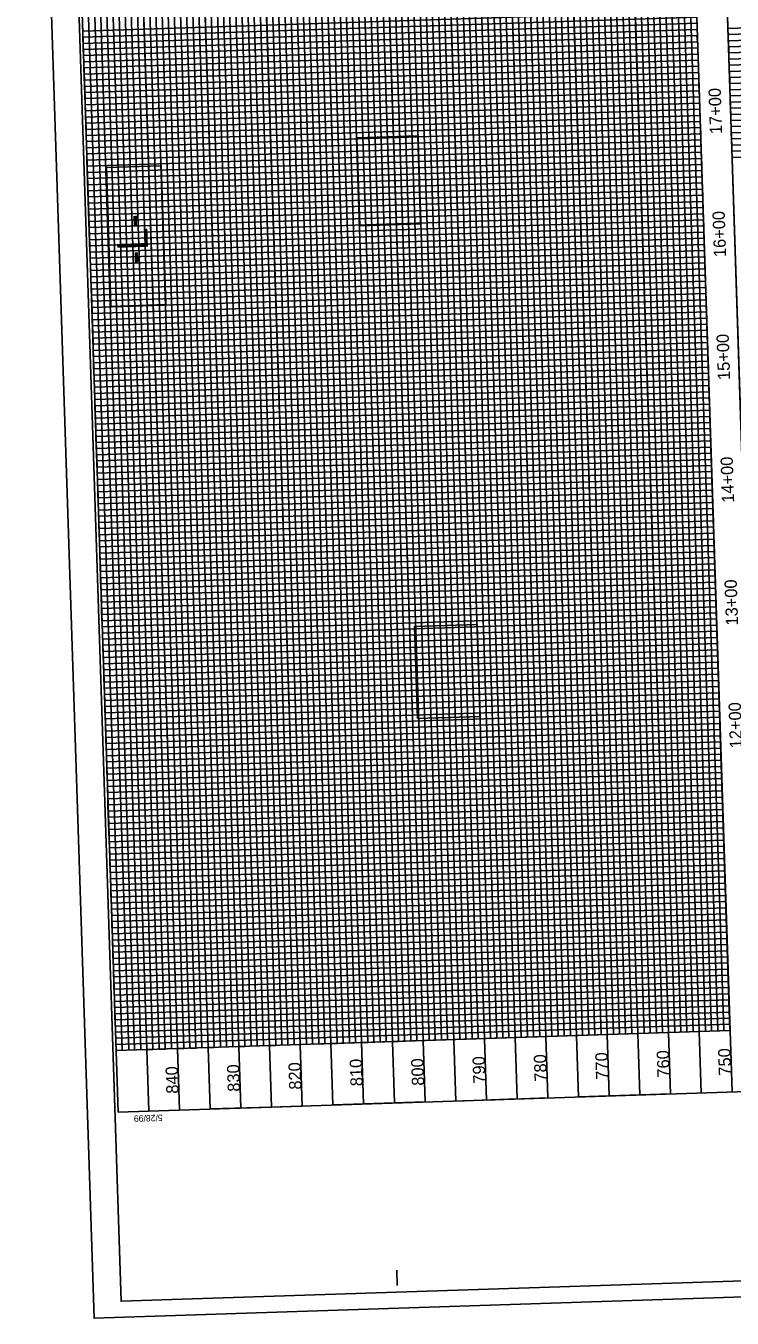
# Model space of a CAD drawing. Extents: x 1627314 to 1628469, y 762309 to 764212.
# Drawn here: x 1627314 to 1627889, y 762309 to 763361 of the extents above; entities that cross this region are included whole.
import ezdxf

# ---------------------------------------------------------------- set-up
doc = ezdxf.new("R2010")
doc.units = 0
for name, color, linetype in [('Exist Vertical Profile Horizontal Axis Label Major', 7, 'Continuous'), ('Exist Vertical Profile Vertical Axis Label', 7, 'Continuous'), ('Prop DSN Text', 7, 'Continuous'), ('Prop Grid Mask', 7, 'Continuous'), ('Sheet DOT Grid CELL', 7, 'Continuous'), ('Sheet Layout Profile Border Port 1', 7, 'Continuous'), ('Sheet Layout Profile Border Port 2', 7, 'Continuous'), ('Sheet Plot Border Inside CELL', 7, 'Continuous'), ('Sheet Plot Border Outside CELL', 7, 'Continuous'), ('Sheet Profile CELL', 7, 'Continuous'), ('Sheet Profile Grid Major CELL', 7, 'Continuous'), ('Sheet Profile Grid Middle CELL', 7, 'Continuous'), ('Sheet Profile Grid Minor CELL', 7, 'Continuous')]:
    doc.layers.add(name, color=color, linetype=linetype)

msp = doc.modelspace()

# ---------------------------------------------------------------- linework, layer by layer
at = {"layer": 'Prop Grid Mask'}
for points in [[(1627586, 763198), (1627583.6, 763269.6), (1627633.2, 763271.3), (1627635.6, 763199.6)], [(1627428.2, 763134), (1627424.5, 763247), (1627379.8, 763245.6), (1627383.5, 763132.5)], [(1627633.1, 762797.2), (1627630.7, 762872), (1627681.6, 762873.7), (1627684.1, 762798.8)]]:
    msp.add_lwpolyline(points, close=True, dxfattribs=at)
at = {"layer": 'Sheet DOT Grid CELL'}
for p, q in [((1627914, 762494.2), (1627865, 763993.3)), ((1627590.1, 763984.4), (1627639.2, 762485.2)), ((1627640.1, 763986), (1627689.2, 762486.8)), ((1627690.1, 763987.7), (1627739.1, 762488.5)), ((1627740.1, 763989.3), (1627789.1, 762490.1)), ((1627790, 763991), (1627839.1, 762491.8)), ((1627546.7, 763782.8), (1627589.2, 762483.6)), ((1627396.8, 763777.9), (1627439.3, 762478.7)), ((1627446.8, 763779.6), (1627489.3, 762480.3)), ((1627496.7, 763781.3), (1627539.2, 762481.9)), ((1627886.3, 763343.8), (1628386, 763360.1)), ((1627861.3, 763342.9), (1627361.5, 763326.6)), ((1627887.9, 763293.8), (1628387.6, 763310.1)), ((1627862.9, 763293), (1627363.2, 763276.6)), ((1627864.5, 763243), (1627364.8, 763226.6)), ((1627866.2, 763193), (1627366.4, 763176.7)), ((1627867.8, 763143), (1627368.1, 763126.7)), ((1627869.4, 763093.1), (1627369.7, 763076.7)), ((1627871.1, 763043.1), (1627371.3, 763026.7)), ((1627872.7, 762993.1), (1627373, 762976.8)), ((1627874.3, 762943.1), (1627374.6, 762926.8)), ((1627876, 762893.2), (1627376.2, 762876.8)), ((1627877.6, 762843.2), (1627377.9, 762826.9)), ((1627879.2, 762793.2), (1627379.5, 762776.9)), ((1627880.9, 762743.3), (1627381.1, 762726.9)), ((1627882.5, 762693.3), (1627382.8, 762676.9)), ((1627884.2, 762643.3), (1627384.4, 762627)), ((1627885.8, 762593.3), (1627386.1, 762577)), ((1627887.4, 762543.4), (1627387.7, 762527))]:
    msp.add_line(p, q, dxfattribs=at)
at = {"layer": 'Sheet Layout Profile Border Port 1'}
msp.add_lwpolyline([(1627386.1, 762577), (1627885.8, 762593.3), (1627841.7, 763942.6), (1627566.8, 763933.6), (1627570.1, 763833.6), (1627345.2, 763826.3)], close=True, dxfattribs=at)
msp.add_lwpolyline([(1627548.7, 762532.3), (1627887.4, 762543.4), (1627841.7, 763942.6), (1627566.8, 763933.6)], dxfattribs=at)
at = {"layer": 'Sheet Layout Profile Border Port 2'}
for points in [[(1627912.4, 762544.2), (1627866.6, 763943.4), (1628366.4, 763959.8), (1628412.1, 762560.5)], [(1627912.4, 762544.2), (1628412.1, 762560.5), (1628366.4, 763959.8), (1627866.6, 763943.4)]]:
    msp.add_lwpolyline(points, close=True, dxfattribs=at)
at = {"layer": 'Sheet Plot Border Inside CELL'}
msp.add_lwpolyline([(1628446.3, 762357.5), (1628391.9, 764023.1), (1627337.3, 763988.6), (1627391.8, 762323)], close=True, dxfattribs=at)
at = {"layer": 'Sheet Plot Border Outside CELL'}
msp.add_lwpolyline([(1628469.2, 762345.3), (1628413.6, 764044.4), (1627314.2, 764008.4), (1627369.8, 762309.3)], close=True, dxfattribs=at)
at = {"layer": 'Sheet Profile CELL'}
for p, q in [((1627889.1, 762493.4), (1627840, 763992.6)), ((1627914, 762494.2), (1627865, 763993.4)), ((1627616.6, 762335.9), (1627616.1, 762348.4))]:
    msp.add_line(p, q, dxfattribs=at)
msp.add_lwpolyline([(1627340.3, 763976.2), (1627389.3, 762477), (1628438.8, 762511.4), (1628389.7, 764010.6)], close=True, dxfattribs=at)
at = {"layer": 'Sheet Profile Grid Major CELL'}
msp.add_line((1627887.9, 763293.8), (1627886.3, 763343.8), dxfattribs=at)
for points in [[(1627546.7, 763782.9), (1627589.2, 762483.6), (1627639.2, 762485.2), (1627590.1, 763984.4)], [(1627640.1, 763986), (1627689.2, 762486.8), (1627739.1, 762488.5), (1627690.1, 763987.7)], [(1627740.1, 763989.3), (1627789.1, 762490.1), (1627789.1, 762490.1), (1627839.1, 762491.8), (1627790, 763991)], [(1627439.3, 762478.7), (1627396.8, 763778)], [(1627446.8, 763779.6), (1627489.3, 762480.3), (1627539.2, 762481.9), (1627496.7, 763781.3)], [(1627387.7, 762527), (1627887.4, 762543.4), (1627885.8, 762593.3), (1627386.1, 762577), (1627384.4, 762627), (1627884.2, 762643.3), (1627882.5, 762693.3), (1627382.8, 762676.9), (1627381.1, 762726.9), (1627880.9, 762743.3), (1627879.2, 762793.2), (1627379.5, 762776.9), (1627377.9, 762826.9), (1627877.6, 762843.2), (1627876, 762893.2), (1627376.2, 762876.8), (1627374.6, 762926.8), (1627874.3, 762943.1), (1627872.7, 762993.1), (1627373, 762976.8), (1627371.3, 763026.7), (1627871.1, 763043.1), (1627869.4, 763093.1), (1627369.7, 763076.7), (1627368.1, 763126.7), (1627867.8, 763143), (1627866.2, 763193), (1627366.4, 763176.7), (1627364.8, 763226.6), (1627864.5, 763243), (1627862.9, 763293), (1627363.2, 763276.6), (1627361.5, 763326.6), (1627861.3, 763342.9), (1627859.6, 763392.9)], [(1628387.6, 763310.1), (1627887.9, 763293.8), (1627886.3, 763343.8), (1628386, 763360.1)]]:
    msp.add_lwpolyline(points, dxfattribs=at)
at = {"layer": 'Sheet Profile Grid Middle CELL'}
msp.add_line((1627414.3, 762477.9), (1627371.8, 763777.1), dxfattribs=at)
for points in [[(1627615.1, 763985.2), (1627664.2, 762486), (1627714.1, 762487.7), (1627665.1, 763986.9)], [(1627715.1, 763988.5), (1627764.1, 762489.3), (1627814.1, 762490.9), (1627765.1, 763990.1)], [(1627815, 763991.8), (1627864.1, 762492.6)], [(1627521.7, 763782), (1627564.2, 762482.8), (1627614.2, 762484.4), (1627570.9, 763808.7)], [(1627421.8, 763778.8), (1627464.3, 762479.5), (1627514.3, 762481.1), (1627471.8, 763780.4)], [(1627386.9, 762552), (1627886.6, 762568.3), (1627885, 762618.3), (1627385.2, 762602), (1627383.6, 762651.9), (1627883.3, 762668.3), (1627881.7, 762718.3), (1627382, 762701.9), (1627380.3, 762751.9), (1627880.1, 762768.2), (1627878.4, 762818.2), (1627378.7, 762801.9), (1627377.1, 762851.8), (1627876.8, 762868.2), (1627875.2, 762918.2), (1627375.4, 762901.8), (1627373.8, 762951.8), (1627873.5, 762968.1), (1627871.9, 763018.1), (1627372.2, 763001.8), (1627370.5, 763051.7), (1627870.3, 763068.1), (1627868.6, 763118.1), (1627868.6, 763118.1), (1627368.9, 763101.7), (1627367.3, 763151.7), (1627867, 763168), (1627865.4, 763218), (1627365.6, 763201.7), (1627364, 763251.6), (1627863.7, 763268), (1627862.1, 763317.9), (1627362.4, 763301.6), (1627360.7, 763351.6), (1627860.4, 763367.9)], [(1628386.8, 763335.1), (1627887.1, 763318.8), (1627885.4, 763368.7)], [(1627890.3, 763218.8), (1627888.7, 763268.8), (1628388.4, 763285.1)]]:
    msp.add_lwpolyline(points, dxfattribs=at)
at = {"layer": 'Sheet Profile Grid Minor CELL'}
for p, q in [((1627792.5, 762540.3), (1627746.7, 763939.5)), ((1627751.7, 763939.7), (1627797.5, 762540.4)), ((1627802.5, 762540.6), (1627756.7, 763939.8)), ((1627761.7, 763940), (1627807.5, 762540.7)), ((1627817.5, 762541.1), (1627771.7, 763940.3)), ((1627776.7, 763940.5), (1627822.5, 762541.2)), ((1627827.5, 762541.4), (1627781.7, 763940.7)), ((1627786.7, 763940.8), (1627832.4, 762541.6)), ((1627842.4, 762541.9), (1627796.7, 763941.1)), ((1627801.7, 763941.3), (1627847.4, 762542.1)), ((1627852.4, 762542.2), (1627806.7, 763941.5)), ((1627811.7, 763941.6), (1627857.4, 762542.4)), ((1627867.4, 762542.7), (1627821.7, 763942)), ((1627826.7, 763942.1), (1627872.4, 762542.9)), ((1627877.4, 762543), (1627831.7, 763942.3)), ((1627576.8, 763933.9), (1627622.6, 762534.7)), ((1627627.6, 762534.9), (1627581.8, 763934.1)), ((1627586.8, 763934.3), (1627632.6, 762535)), ((1627642.6, 762535.4), (1627596.8, 763934.6)), ((1627601.8, 763934.8), (1627647.5, 762535.5)), ((1627652.5, 762535.7), (1627606.8, 763934.9)), ((1627611.8, 763935.1), (1627657.5, 762535.8)), ((1627667.5, 762536.2), (1627621.8, 763935.4)), ((1627626.8, 763935.6), (1627672.5, 762536.3)), ((1627677.5, 762536.5), (1627631.8, 763935.7)), ((1627636.8, 763935.9), (1627682.5, 762536.7)), ((1627692.5, 762537), (1627646.8, 763936.2)), ((1627651.8, 763936.4), (1627697.5, 762537.1)), ((1627702.5, 762537.3), (1627656.7, 763936.6)), ((1627661.7, 763936.7), (1627707.5, 762537.5)), ((1627717.5, 762537.8), (1627671.7, 763937.1)), ((1627676.7, 763937.2), (1627722.5, 762538)), ((1627727.5, 762538.1), (1627681.7, 763937.4)), ((1627686.7, 763937.5), (1627732.5, 762538.3)), ((1627742.5, 762538.6), (1627696.7, 763937.9)), ((1627701.7, 763938), (1627747.5, 762538.8)), ((1627752.5, 762538.9), (1627706.7, 763938.2)), ((1627711.7, 763938.4), (1627757.5, 762539.1)), ((1627767.5, 762539.4), (1627721.7, 763938.7)), ((1627726.7, 763938.9), (1627772.5, 762539.6)), ((1627731.7, 763939), (1627777.5, 762539.8)), ((1627736.7, 763939.2), (1627782.5, 762539.9)), ((1627506.7, 763781.6), (1627547.6, 762532.2)), ((1627552.6, 762532.4), (1627511.7, 763781.7)), ((1627531.7, 763782.3), (1627572.6, 762533.1)), ((1627577.6, 762533.2), (1627536.7, 763782.5)), ((1627556.7, 763783.2), (1627597.6, 762533.9)), ((1627602.6, 762534), (1627561.7, 763783.3)), ((1627392.7, 762527.2), (1627351.8, 763776.5)), ((1627356.8, 763776.7), (1627398, 762527.4)), ((1627402.7, 762527.5), (1627361.8, 763776.8)), ((1627481.8, 763780.7), (1627522.6, 762531.4)), ((1627486.7, 763780.9), (1627527.6, 762531.6)), ((1627491.7, 763781.1), (1627532.6, 762531.8)), ((1627542.6, 762532.1), (1627501.7, 763781.4)), ((1627397.7, 762527.3), (1627397.7, 762527.3))]:
    msp.add_line(p, q, dxfattribs=at)
for points in [[(1627836.7, 763942.4), (1627882.4, 762543.2)], [(1627566.7, 763783.5), (1627607.6, 762534.2), (1627617.6, 762534.5), (1627571.8, 763933.8)], [(1627516.7, 763781.9), (1627557.6, 762532.6), (1627567.6, 762532.9), (1627526.7, 763782.2)], [(1627541.7, 763782.7), (1627582.6, 762533.4), (1627592.6, 762533.7), (1627551.7, 763783)], [(1627366.8, 763777), (1627407.7, 762527.7), (1627417.7, 762528), (1627376.8, 763777.3)], [(1627381.8, 763777.4), (1627422.7, 762528.2), (1627427.7, 762528.3), (1627386.8, 763777.7)], [(1627391.8, 763777.8), (1627432.7, 762528.5), (1627442.7, 762528.8), (1627401.8, 763778.1)], [(1627406.8, 763778.3), (1627447.7, 762529), (1627452.7, 762529.1), (1627411.8, 763778.5)], [(1627416.8, 763778.6), (1627457.6, 762529.3), (1627467.6, 762529.6), (1627426.8, 763779)], [(1627431.8, 763779.1), (1627472.6, 762529.8), (1627477.6, 762530), (1627436.8, 763779.3)], [(1627441.8, 763779.5), (1627482.6, 762530.1), (1627492.6, 762530.4), (1627451.8, 763779.8)], [(1627456.9, 763779.9), (1627497.7, 762530.7), (1627502.6, 762530.9), (1627461.8, 763780.1)], [(1627466.8, 763780.3), (1627507.6, 762530.9), (1627517.6, 762531.3), (1627476.8, 763780.6)], [(1627370.4, 763056.7), (1627870.1, 763073.1), (1627869.9, 763078.1), (1627370.2, 763061.7), (1627370, 763066.7), (1627869.8, 763083.1), (1627869.6, 763088.1), (1627369.9, 763071.7), (1627369.5, 763081.7), (1627869.3, 763098.1), (1627869.1, 763103.1), (1627369.4, 763086.7), (1627369.2, 763091.7), (1627868.9, 763108.1), (1627868.8, 763113.1), (1627369.1, 763096.7), (1627368.7, 763106.7), (1627868.5, 763123.1), (1627868.3, 763128), (1627368.6, 763111.7), (1627368.4, 763116.7), (1627868.1, 763133), (1627868, 763138), (1627368.2, 763121.7), (1627367.9, 763131.7), (1627867.6, 763148), (1627867.5, 763153), (1627367.7, 763136.7), (1627367.6, 763141.7), (1627867.3, 763158), (1627867.2, 763163), (1627367.4, 763146.7), (1627367.1, 763156.7), (1627866.8, 763173), (1627866.7, 763178), (1627366.9, 763161.7), (1627366.8, 763166.7), (1627866.5, 763183), (1627866.3, 763188), (1627366.6, 763171.7), (1627366.3, 763181.7), (1627866, 763198), (1627866, 763198), (1627865.8, 763203), (1627366.1, 763186.7), (1627365.9, 763191.7), (1627865.7, 763208), (1627865.5, 763213), (1627365.8, 763196.7), (1627365.5, 763206.7), (1627865.2, 763223), (1627865, 763228), (1627365.3, 763211.6), (1627365.1, 763216.6), (1627864.9, 763233), (1627864.7, 763238), (1627365, 763221.6), (1627364.6, 763231.6), (1627864.4, 763248), (1627864.2, 763253), (1627364.5, 763236.6), (1627364.3, 763241.6), (1627864, 763258), (1627863.9, 763263), (1627364.1, 763246.6), (1627363.8, 763256.6), (1627863.6, 763273), (1627863.4, 763278), (1627363.7, 763261.6), (1627363.5, 763266.6), (1627863.2, 763283), (1627863.1, 763288), (1627363.3, 763271.6), (1627363, 763281.6), (1627862.7, 763298), (1627862.6, 763303), (1627362.8, 763286.6), (1627362.7, 763291.6), (1627862.4, 763308), (1627862.2, 763312.9), (1627362.5, 763296.6), (1627362.2, 763306.6), (1627861.9, 763322.9), (1627861.8, 763327.9), (1627362, 763311.6), (1627361.9, 763316.6), (1627861.6, 763332.9), (1627861.4, 763337.9), (1627361.7, 763321.6), (1627361.4, 763331.6), (1627861.1, 763347.9), (1627860.4, 763352.6), (1627860.9, 763352.9), (1627361.2, 763336.6), (1627361, 763341.6), (1627860.8, 763357.9), (1627860.6, 763362.9), (1627360.9, 763346.6), (1627360.6, 763356.6), (1627860.3, 763372.9)], [(1628385.7, 763370.1), (1627885.9, 763353.7), (1627885.8, 763358.7), (1628385.5, 763375.1)], [(1628386.1, 763355.1), (1627886.4, 763338.8), (1627886.1, 763348.7), (1628385.8, 763365.1)], [(1628386.5, 763345.1), (1627886.7, 763328.8), (1627886.6, 763333.8), (1628386.3, 763350.1)], [(1628387, 763330.1), (1627887.2, 763313.8), (1627886.9, 763323.8), (1628386.6, 763340.1)], [(1628387.3, 763320.1), (1627887.6, 763303.8), (1627887.4, 763308.8), (1628387.1, 763325.1)], [(1628387.8, 763305.1), (1627888.1, 763288.8), (1627887.7, 763298.8), (1628387.5, 763315.1)], [(1628388.1, 763295.1), (1627888.4, 763278.8), (1627888.2, 763283.8), (1628387.9, 763300.1)], [(1628388.6, 763280.1), (1627888.9, 763263.8), (1627888.5, 763273.8), (1628388.3, 763290.1)], [(1628388.9, 763270.1), (1627889.2, 763253.8), (1627889, 763258.8), (1628388.8, 763275.1)], [(1627880.4, 762758.2), (1627880.2, 762763.2), (1627380.5, 762746.9), (1627380.2, 762756.9), (1627879.9, 762773.2), (1627879.7, 762778.2), (1627380, 762761.9), (1627379.8, 762766.9), (1627879.6, 762783.2), (1627879.4, 762788.2), (1627379.7, 762771.9), (1627379.4, 762781.9), (1627879.1, 762798.2), (1627878.9, 762803.2), (1627379.2, 762786.9), (1627379, 762791.9), (1627878.8, 762808.2), (1627878.6, 762813.2), (1627378.9, 762796.9), (1627378.5, 762806.9), (1627878.3, 762823.2), (1627878.1, 762828.2), (1627378.4, 762811.9), (1627378.2, 762816.9), (1627877.9, 762833.2), (1627877.8, 762838.2), (1627378, 762821.9), (1627377.7, 762831.9), (1627877.4, 762848.2), (1627877.3, 762853.2), (1627377.6, 762836.8), (1627377.4, 762841.8), (1627877.1, 762858.2), (1627877, 762863.2), (1627377.2, 762846.8), (1627376.9, 762856.8), (1627876.6, 762873.2), (1627876.5, 762878.2), (1627376.7, 762861.8), (1627376.6, 762866.8), (1627876.3, 762883.2), (1627876.1, 762888.2), (1627376.4, 762871.8), (1627376.1, 762881.8), (1627875.8, 762898.2), (1627875.7, 762903.2), (1627375.9, 762886.8), (1627375.8, 762891.8), (1627875.5, 762908.2), (1627875.3, 762913.2), (1627375.6, 762896.8), (1627375.3, 762906.8), (1627875, 762923.2), (1627874.8, 762928.2), (1627375.1, 762911.8), (1627374.9, 762916.8), (1627874.7, 762933.2), (1627874.5, 762938.1), (1627374.8, 762921.8), (1627374.4, 762931.8), (1627874.2, 762948.1), (1627874, 762953.1), (1627374.3, 762936.8), (1627374.1, 762941.8), (1627873.9, 762958.1), (1627873.7, 762963.1), (1627374, 762946.8), (1627373.6, 762956.8), (1627873.4, 762973.1), (1627873.2, 762978.1), (1627373.5, 762961.8), (1627373.3, 762966.8), (1627873, 762983.1), (1627872.9, 762988.1), (1627373.1, 762971.8), (1627372.8, 762981.8), (1627872.5, 762998.1), (1627872.4, 763003.1), (1627372.6, 762986.8), (1627372.5, 762991.8), (1627872.2, 763008.1), (1627872.1, 763013.1), (1627372.3, 762996.8), (1627372, 763006.8), (1627871.7, 763023.1), (1627871.6, 763028.1), (1627371.8, 763011.8), (1627371.7, 763016.8), (1627871.4, 763033.1), (1627871.2, 763038.1), (1627371.5, 763021.7), (1627371.2, 763031.7), (1627870.9, 763048.1), (1627870.7, 763053.1), (1627371, 763036.7), (1627370.9, 763041.7), (1627870.6, 763058.1), (1627870.4, 763063.1), (1627370.7, 763046.7), (1627370.4, 763056.7)], [(1627387.5, 762532), (1627887.3, 762548.4), (1627887.1, 762553.4), (1627387.4, 762537), (1627387.2, 762542), (1627886.9, 762558.4), (1627886.8, 762563.4), (1627387, 762547), (1627386.7, 762557), (1627886.4, 762573.3), (1627886.3, 762578.3), (1627386.5, 762562), (1627386.4, 762567), (1627886.1, 762583.3), (1627885.9, 762588.3), (1627885.6, 762598.3), (1627885.5, 762603.3), (1627385.7, 762587), (1627385.6, 762592), (1627885.3, 762608.3), (1627885.1, 762613.3), (1627385.4, 762597), (1627385.1, 762607), (1627884.8, 762623.3), (1627884.6, 762628.3), (1627384.9, 762612), (1627384.7, 762617), (1627884.5, 762633.3), (1627884.3, 762638.3), (1627384.6, 762622), (1627384.3, 762632), (1627884, 762648.3), (1627883.8, 762653.3), (1627384.1, 762637), (1627383.9, 762642), (1627883.7, 762658.3), (1627883.5, 762663.3), (1627383.8, 762647), (1627383.4, 762656.9), (1627883.2, 762673.3), (1627883, 762678.3), (1627383.3, 762661.9), (1627383.1, 762666.9), (1627882.8, 762683.3), (1627882.7, 762688.3), (1627382.9, 762671.9), (1627382.6, 762681.9), (1627882.4, 762698.3), (1627882.2, 762703.3), (1627382.5, 762686.9), (1627382.3, 762691.9), (1627882, 762708.3), (1627881.9, 762713.3), (1627382.1, 762696.9), (1627381.8, 762706.9), (1627881.5, 762723.3), (1627881.4, 762728.3), (1627381.6, 762711.9), (1627381.5, 762716.9), (1627881.2, 762733.3), (1627881, 762738.3), (1627381.3, 762721.9), (1627381, 762731.9), (1627880.7, 762748.3), (1627880.6, 762753.2), (1627380.8, 762736.9), (1627380.7, 762741.9), (1627880.4, 762758.2)], [(1627885.9, 762588.3), (1627386.2, 762572), (1627385.9, 762582), (1627885.6, 762598.3)]]:
    msp.add_lwpolyline(points, dxfattribs=at)

# ---------------------------------------------------------------- texts
at = {"layer": 'Exist Vertical Profile Horizontal Axis Label Major'}
for s, p in [('17+00', (1627881.1, 763272.9)), ('16+00', (1627884.3, 763172.8)), ('15+00', (1627887.6, 763072.8)), ('14+00', (1627890.9, 762972.9)), ('13+00', (1627894.1, 762873)), ('12+00', (1627897.4, 762773.1))]:
    msp.add_text(s, height=10, rotation=91.8735, dxfattribs=at).set_placement(p)
at = {"layer": 'Exist Vertical Profile Vertical Axis Label'}
for s, p in [('810', (1627588.5, 762498.2)), ('800', (1627638.5, 762498.6)), ('790', (1627688.5, 762500.3)), ('780', (1627738.4, 762501.9)), ('770', (1627788.4, 762503.5)), ('760', (1627838.4, 762505.2)), ('750', (1627888.4, 762506.8)), ('840', (1627438.6, 762492.1)), ('830', (1627488.6, 762493.7)), ('820', (1627538.6, 762495.4))]:
    msp.add_text(s, height=10, rotation=91.8735, dxfattribs=at).set_placement(p)
at = {"layer": 'Prop DSN Text'}
msp.add_text('-L-', height=25, rotation=91.8735, dxfattribs=at).set_placement((1627414.1, 763167.2))
at = {"layer": 'Sheet Profile CELL'}
msp.add_text('5/28/99', height=5.25, rotation=181.8735, dxfattribs=at).set_placement((1627425.5, 762475))

doc.saveas('drawing.dxf')
